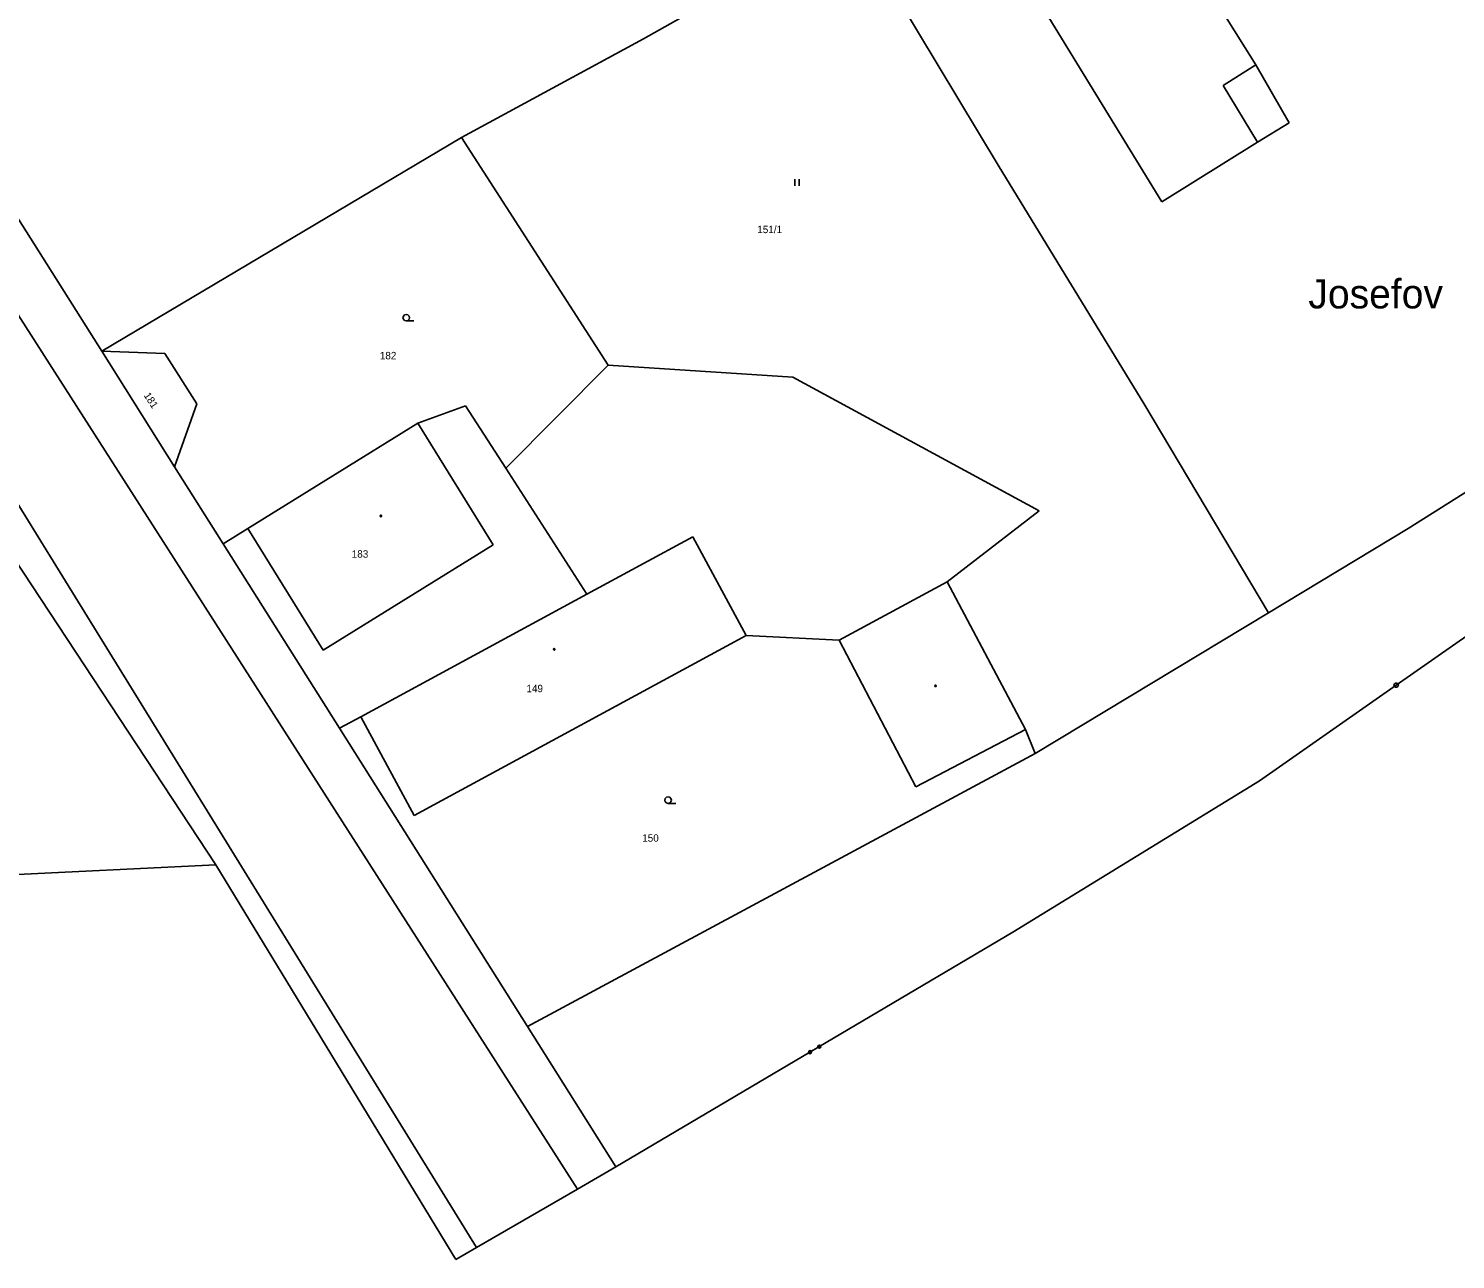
# Model space of a CAD drawing. Extents: x -871430 to -870620, y -1010094 to -1009649.
# Drawn here: x -870905.1 to -870823.3, y -1010084.6 to -1010013.9 of the extents above; entities that cross this region are included whole.
import ezdxf

# ---------------------------------------------------------------- set-up
doc = ezdxf.new("R2010")
doc.units = 0
for name, color, linetype in [('Vrstva 1', 7, 'Continuous'), ('Vrstva 2', 7, 'Continuous'), ('Vrstva 3', 7, 'Continuous'), ('Vrstva 4', 7, 'Continuous'), ('Vrstva 5', 7, 'Continuous'), ('Vrstva 7', 7, 'Continuous'), ('Vrstva 8', 7, 'Continuous')]:
    doc.layers.add(name, color=color, linetype=linetype)

msp = doc.modelspace()

# ---------------------------------------------------------------- linework, layer by layer
at = {"layer": 'Vrstva 1'}
for p, q in [((-870900.92, -1010032.45), (-870917.34, -1010006.41)), ((-870840.12, -1010023.87), (-870850.37, -1010007.15)), ((-870857.92, -1010007.79), (-870849.45, -1010021.86)), ((-870837.87, -1010010.98), (-870834.73, -1010016.02)), ((-870864.43, -1010011.46), (-870869.85, -1010014.52)), ((-870869.85, -1010014.52), (-870880.28, -1010020.18)), ((-870834.73, -1010016.02), (-870832.82, -1010019.34)), ((-870832.82, -1010019.34), (-870834.63, -1010020.46)), ((-870880.28, -1010020.18), (-870900.92, -1010032.45)), ((-870871.87, -1010033.24), (-870880.28, -1010020.18)), ((-870834.63, -1010020.46), (-870840.12, -1010023.87)), ((-870849.45, -1010021.86), (-870841.16, -1010035.45)), ((-870900.92, -1010032.45), (-870897.3, -1010032.57)), ((-870900.92, -1010032.45), (-870896.75, -1010039.07)), ((-870897.3, -1010032.57), (-870895.47, -1010035.47)), ((-870871.87, -1010033.24), (-870877.75, -1010039.16)), ((-870861.29, -1010033.94), (-870871.87, -1010033.24)), ((-870847.15, -1010041.6), (-870861.29, -1010033.94)), ((-870896.75, -1010039.07), (-870895.47, -1010035.47)), ((-870841.16, -1010035.45), (-870834, -1010047.46)), ((-870882.8, -1010036.57), (-870880.06, -1010035.58)), ((-870880.06, -1010035.58), (-870877.75, -1010039.16)), ((-870892.55, -1010042.61), (-870882.8, -1010036.57)), ((-870817.77, -1010037.43), (-870826, -1010042.62)), ((-870896.75, -1010039.07), (-870893.96, -1010043.49)), ((-870877.75, -1010039.16), (-870873.09, -1010046.38)), ((-870852.44, -1010045.68), (-870847.15, -1010041.6)), ((-870894.37, -1010061.92), (-870907.27, -1010042.34)), ((-870893.96, -1010043.49), (-870892.55, -1010042.61)), ((-870826, -1010042.62), (-870834, -1010047.46)), ((-870887.29, -1010054.08), (-870893.96, -1010043.49)), ((-870847.94, -1010054.15), (-870852.44, -1010045.68)), ((-870873.09, -1010046.38), (-870886.07, -1010053.42)), ((-870834, -1010047.46), (-870847.39, -1010055.52)), ((-870863.96, -1010048.75), (-870883, -1010059.08)), ((-870863.96, -1010048.75), (-870858.63, -1010049.02)), ((-870858.63, -1010049.02), (-870854.23, -1010057.44)), ((-870826.68, -1010051.61), (-870822.43, -1010048.64)), ((-870834.52, -1010057.09), (-870826.68, -1010051.61)), ((-870887.29, -1010054.08), (-870886.07, -1010053.42)), ((-870883, -1010059.08), (-870886.07, -1010053.42)), ((-870876.51, -1010071.19), (-870887.29, -1010054.08)), ((-870854.23, -1010057.44), (-870847.94, -1010054.15)), ((-870847.39, -1010055.52), (-870847.94, -1010054.15)), ((-870847.39, -1010055.52), (-870876.51, -1010071.19)), ((-870848.66, -1010065.78), (-870834.52, -1010057.09)), ((-870915.49, -1010062.94), (-870894.37, -1010061.92)), ((-870894.37, -1010061.92), (-870888.64, -1010071.35)), ((-870871.43, -1010079.24), (-870848.66, -1010065.78)), ((-870888.64, -1010071.35), (-870880.61, -1010084.56)), ((-870871.43, -1010079.24), (-870876.51, -1010071.19)), ((-870873.64, -1010080.52), (-870871.43, -1010079.24)), ((-870879.42, -1010083.87), (-870873.64, -1010080.52)), ((-870880.61, -1010084.56), (-870879.42, -1010083.87))]:
    msp.add_line(p, q, dxfattribs=at)
for points in [[(-870859.778, -1010072.259), (-870859.713, -1010072.276), (-870859.679, -1010072.334), (-870859.695, -1010072.399), (-870859.753, -1010072.433), (-870859.818, -1010072.417), (-870859.853, -1010072.359), (-870859.836, -1010072.294), (-870859.778, -1010072.259), (-870859.779, -1010072.272), (-870859.831, -1010072.302), (-870859.838, -1010072.33), (-870859.752, -1010072.279), (-870859.725, -1010072.286), (-870859.845, -1010072.357), (-870859.835, -1010072.374), (-870859.714, -1010072.303), (-870859.704, -1010072.32), (-870859.825, -1010072.391), (-870859.815, -1010072.409), (-870859.694, -1010072.337), (-870859.701, -1010072.365), (-870859.787, -1010072.416), (-870859.76, -1010072.423), (-870859.708, -1010072.392)], [(-870860.316, -1010072.577), (-870860.251, -1010072.594), (-870860.217, -1010072.652), (-870860.233, -1010072.717), (-870860.291, -1010072.752), (-870860.356, -1010072.735), (-870860.391, -1010072.677), (-870860.374, -1010072.612), (-870860.316, -1010072.577), (-870860.313, -1010072.587), (-870860.365, -1010072.618), (-870860.372, -1010072.645), (-870860.286, -1010072.594), (-870860.258, -1010072.601), (-870860.379, -1010072.672), (-870860.369, -1010072.69), (-870860.248, -1010072.618), (-870860.238, -1010072.636), (-870860.358, -1010072.707), (-870860.348, -1010072.724), (-870860.228, -1010072.653), (-870860.235, -1010072.68), (-870860.321, -1010072.731), (-870860.293, -1010072.738), (-870860.242, -1010072.708)]]:
    msp.add_lwpolyline(points, dxfattribs=at)
at = {"layer": 'Vrstva 3'}
for p, q in [((-870861.165, -1010022.575), (-870861.165, -1010022.95)), ((-870860.915, -1010022.95), (-870860.915, -1010022.575))]:
    msp.add_line(p, q, dxfattribs=at)
for points in [[(-870883.46, -1010030.71), (-870883.555, -1010030.685), (-870883.622, -1010030.615), (-870883.648, -1010030.522), (-870883.622, -1010030.43), (-870883.555, -1010030.36), (-870883.46, -1010030.335), (-870883.365, -1010030.36), (-870883.298, -1010030.43), (-870883.272, -1010030.522), (-870883.298, -1010030.615), (-870883.365, -1010030.685), (-870883.46, -1010030.71), (-870883.022, -1010030.71)], [(-870868.44, -1010058.39), (-870868.535, -1010058.365), (-870868.602, -1010058.295), (-870868.628, -1010058.202), (-870868.602, -1010058.11), (-870868.535, -1010058.04), (-870868.44, -1010058.015), (-870868.345, -1010058.04), (-870868.278, -1010058.11), (-870868.252, -1010058.202), (-870868.278, -1010058.295), (-870868.345, -1010058.365), (-870868.44, -1010058.39), (-870868.002, -1010058.39)]]:
    msp.add_lwpolyline(points, dxfattribs=at)
at = {"layer": 'Vrstva 4'}
for p, q in [((-870921.37, -1010015.86), (-870879.42, -1010083.87)), ((-870834.73, -1010016.02), (-870836.61, -1010017.2)), ((-870873.64, -1010080.52), (-870914.33, -1010016.91)), ((-870836.61, -1010017.2), (-870834.63, -1010020.46)), ((-870878.47, -1010043.56), (-870882.8, -1010036.57)), ((-870892.55, -1010042.61), (-870888.22, -1010049.6)), ((-870888.22, -1010049.6), (-870878.47, -1010043.56)), ((-870867.02, -1010043.09), (-870873.09, -1010046.38)), ((-870863.96, -1010048.75), (-870867.02, -1010043.09)), ((-870858.63, -1010049.02), (-870852.44, -1010045.68))]:
    msp.add_line(p, q, dxfattribs=at)
at = {"layer": 'Vrstva 5'}
for points in [[(-870884.91, -1010041.858), (-870884.885, -1010041.862), (-870884.872, -1010041.885), (-870884.868, -1010041.9), (-870884.872, -1010041.922), (-870884.893, -1010041.94), (-870884.91, -1010041.942), (-870884.932, -1010041.935), (-870884.948, -1010041.92), (-870884.952, -1010041.9), (-870884.948, -1010041.878), (-870884.928, -1010041.86), (-870884.91, -1010041.858)], [(-870874.97, -1010049.508), (-870874.945, -1010049.513), (-870874.932, -1010049.535), (-870874.928, -1010049.55), (-870874.932, -1010049.572), (-870874.952, -1010049.59), (-870874.97, -1010049.592), (-870874.992, -1010049.585), (-870875.008, -1010049.57), (-870875.012, -1010049.55), (-870875.008, -1010049.528), (-870874.987, -1010049.51), (-870874.97, -1010049.508)], [(-870853.078, -1010051.612), (-870853.055, -1010051.65), (-870853.078, -1010051.688), (-870853.122, -1010051.688), (-870853.145, -1010051.65), (-870853.122, -1010051.612), (-870853.078, -1010051.612)]]:
    msp.add_lwpolyline(points, dxfattribs=at)
at = {"layer": 'Vrstva 8'}
msp.add_line((-870826.692, -1010051.61), (-870826.668, -1010051.61), dxfattribs=at)
msp.add_lwpolyline([(-870826.643, -1010051.49), (-870826.58, -1010051.538), (-870826.555, -1010051.61), (-870826.58, -1010051.682), (-870826.643, -1010051.73), (-870826.718, -1010051.73), (-870826.78, -1010051.682), (-870826.805, -1010051.61), (-870826.78, -1010051.538), (-870826.718, -1010051.49), (-870826.643, -1010051.49)], dxfattribs=at)

# ---------------------------------------------------------------- texts
at = {"layer": 'Vrstva 2'}
for s, p in [('151/1', (-870863.322, -1010025.67)), ('182', (-870884.972, -1010032.91)), ('183', (-870886.582, -1010044.29)), ('149', (-870876.562, -1010052.01)), ('150', (-870869.922, -1010060.59))]:
    msp.add_text(s, height=0.425, dxfattribs=at).set_placement(p)
msp.add_text('181', height=0.425, rotation=303.09467, dxfattribs=at).set_placement((-870898.529, -1010034.979))
at = {"layer": 'Vrstva 7'}
msp.add_text('Josefov', height=1.675, dxfattribs=at).set_placement((-870831.714, -1010029.99))

doc.saveas('drawing.dxf')
